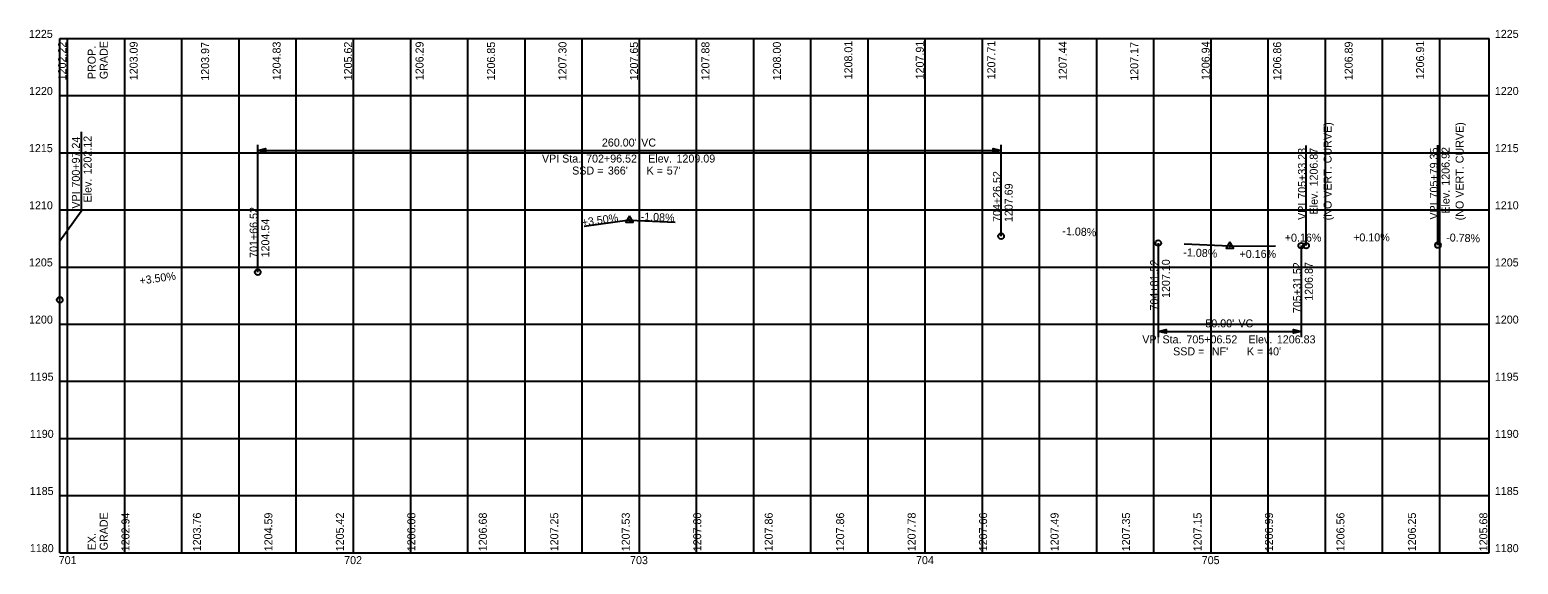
# Model space of a CAD drawing. Extents: x 65 to 585, y 1176 to 1363.
import ezdxf

# ---------------------------------------------------------------- set-up
doc = ezdxf.new("R2010")
doc.units = 0
for name, color, linetype in [('PF_P_Sta_Elev_Text', 7, 'Continuous'), ('PF_P_Text', 7, 'Continuous'), ('PF_P_Text_Strip_Grades_20', 7, 'Continuous'), ('PF_X_Text_Strip_Grade', 7, 'Continuous'), ('SH_Major_Grid_Line', 7, 'Continuous')]:
    doc.layers.add(name, color=color, linetype=linetype)

msp = doc.modelspace()

# ---------------------------------------------------------------- linework, layer by layer
at = {"layer": 'PF_P_Text'}
for p, q in [((144.39, 1278.18), (144.39, 1322.76)), ((404.39, 1290.76), (404.39, 1322.76)), ((557.22, 1287.66), (557.22, 1322.66)), ((144.39, 1320.86), (144.39, 1320.66)), ((144.39, 1320.76), (404.39, 1320.76)), ((404.39, 1320.66), (404.39, 1320.86)), ((511.1, 1287.48), (511.1, 1322.48)), ((75.11, 1268.48), (75.11, 1303.48)), ((274.39, 1296.38), (258.54, 1294.16)), ((274.39, 1296.38), (274.39, 1296.38)), ((274.39, 1296.38), (290.37, 1295.69)), ((459.39, 1288.39), (459.39, 1255.47)), ((484.39, 1287.31), (468.4, 1288)), ((484.39, 1287.31), (500.39, 1287.41)), ((484.39, 1287.31), (484.39, 1287.31)), ((509.39, 1287.47), (509.39, 1255.47)), ((459.39, 1257.57), (459.39, 1257.37)), ((459.39, 1257.47), (509.39, 1257.47)), ((509.39, 1257.37), (509.39, 1257.57))]:
    msp.add_line(p, q, dxfattribs=at)
msp.add_lwpolyline([(82.64, 1327.35), (82.64, 1299.4), (75.11, 1289.05)], dxfattribs=at)
for points in [[(144.39, 1320.76), (147.1, 1321.44), (147.1, 1320.08)], [(404.39, 1320.76), (401.67, 1320.08), (401.67, 1321.44)], [(274.39, 1297.82), (273.14, 1295.66), (275.64, 1295.66)], [(484.39, 1288.75), (483.14, 1286.58), (485.64, 1286.58)], [(459.39, 1257.47), (462.1, 1258.14), (462.1, 1256.79)], [(509.39, 1257.47), (506.67, 1256.79), (506.67, 1258.14)]]:
    msp.add_lwpolyline(points, close=True, dxfattribs=at)
for centre, radius in [((274.39, 1296.38), 0.1), ((274.39, 1296.38), 0.1), ((404.39, 1290.76), 1), ((459.39, 1288.39), 1), ((484.39, 1287.31), 0.1), ((484.39, 1287.31), 0.1), ((509.39, 1287.47), 1), ((511.1, 1287.48), 1), ((557.22, 1287.66), 1), ((144.39, 1278.18), 1), ((75.11, 1268.48), 1)]:
    msp.add_circle(centre, radius, dxfattribs=at)
at = {"layer": 'SH_Major_Grid_Line'}
for p, q in [((75.11, 1360), (575.11, 1360)), ((75.11, 1180), (75.11, 1360)), ((77.87, 1180), (77.87, 1360)), ((97.87, 1180), (97.87, 1360)), ((117.87, 1180), (117.87, 1360)), ((137.87, 1180), (137.87, 1360)), ((157.87, 1180), (157.87, 1360)), ((177.87, 1180), (177.87, 1360)), ((197.87, 1180), (197.87, 1360)), ((217.87, 1180), (217.87, 1360)), ((237.87, 1180), (237.87, 1360)), ((257.87, 1180), (257.87, 1360)), ((277.87, 1180), (277.87, 1360)), ((297.87, 1180), (297.87, 1360)), ((317.87, 1180), (317.87, 1360)), ((337.87, 1180), (337.87, 1360)), ((357.87, 1180), (357.87, 1360)), ((377.87, 1180), (377.87, 1360)), ((397.87, 1180), (397.87, 1360)), ((417.87, 1180), (417.87, 1360)), ((437.87, 1180), (437.87, 1360)), ((457.87, 1180), (457.87, 1360)), ((477.87, 1180), (477.87, 1360)), ((497.87, 1180), (497.87, 1360)), ((517.87, 1180), (517.87, 1360)), ((537.87, 1180), (537.87, 1360)), ((557.87, 1180), (557.87, 1360)), ((575.11, 1180), (575.11, 1360)), ((75.11, 1340), (575.11, 1340)), ((75.11, 1320), (575.11, 1320)), ((75.11, 1300), (575.11, 1300)), ((75.11, 1280), (575.11, 1280)), ((75.11, 1260), (575.11, 1260)), ((75.11, 1240), (575.11, 1240)), ((75.11, 1220), (575.11, 1220)), ((75.11, 1200), (575.11, 1200)), ((75.11, 1180), (575.11, 1180))]:
    msp.add_line(p, q, dxfattribs=at)

# ---------------------------------------------------------------- texts
at = {"layer": 'PF_P_Sta_Elev_Text'}
for s, p in [('1225', (64.34, 1360.2)), ('1225', (577.11, 1360.2)), ('1220', (64.37, 1340.2)), ('1220', (577.11, 1340.2)), ('1215', (64.34, 1320.2)), ('1215', (577.11, 1320.2)), ('1210', (64.37, 1300.2)), ('1210', (577.11, 1300.2)), ('1205', (64.34, 1280.2)), ('1205', (577.11, 1280.2)), ('1200', (64.37, 1260.2)), ('1200', (577.11, 1260.2)), ('1195', (64.63, 1240.2)), ('1195', (577.11, 1240.2)), ('1190', (64.66, 1220.2)), ('1190', (577.11, 1220.2)), ('1185', (64.63, 1200.2)), ('1185', (577.11, 1200.2)), ('1180', (64.66, 1180.2)), ('1180', (577.11, 1180.2)), ('701', (74.76, 1176)), ('702', (174.6, 1176)), ('703', (274.61, 1176)), ('704', (374.63, 1176)), ('705', (474.58, 1176))]:
    msp.add_text(s, height=2.8, dxfattribs=at).set_placement(p)
at = {"layer": 'PF_P_Text'}
for s, rotation, p in [('PROP.', 90, (87.7, 1345.76)), ('GRADE', 90, (91.9, 1345.76)), ('(NO VERT. CURVE)', 90, (520.01, 1296.34)), ('(NO VERT. CURVE)', 90, (566.19, 1296.34)), ('700+97.24', 90, (82.16, 1307.81)), ('1202.12', 90, (86.24, 1312.38)), ('705+33.23', 90, (511.05, 1303.88)), ('1206.87', 90, (515.15, 1308.19)), ('705+79.35', 90, (557.17, 1304)), ('1206.92', 90, (561.27, 1308.46)), ('704+26.52', 90, (404.34, 1295.76)), ('Elev. ', 90, (86.24, 1302.59)), ('1207.69', 90, (408.44, 1295.71)), ('VPI ', 90, (82.16, 1300.42)), ('VPI ', 90, (511.05, 1296.49)), ('Elev. ', 90, (515.15, 1298.41)), ('VPI ', 90, (557.17, 1296.61)), ('Elev. ', 90, (561.27, 1298.68)), ('701+66.52', 90, (144.34, 1283.18)), ('1204.54', 90, (148.42, 1283.35)), ('+3.50%', 7.9696, (257.92, 1294.18)), ('-1.08%', 357.5264, (278.26, 1296.31)), ('-1.08%', 357.5264, (425.77, 1291.24)), ('+0.16%', 0.3667, (503.63, 1288.83)), ('+0.10%', 0.2292, (527.54, 1288.94)), ('-0.78%', 358.213, (560.04, 1288.97)), ('-1.08%', 357.5264, (468.1, 1283.81)), ('704+81.52', 90, (459.34, 1264.77)), ('1207.10', 90, (463.44, 1269.16)), ('+0.16%', 0.3667, (487.8, 1283.13)), ('705+31.52', 90, (509.34, 1263.85)), ('1206.87', 90, (513.44, 1268.19)), ('+3.50%', 7.9696, (103.2, 1273.81)), ('GRADE', 90, (91.9, 1180.83)), ('EX. ', 90, (87.7, 1180.83))]:
    msp.add_text(s, height=2.8, rotation=rotation, dxfattribs=at).set_placement(p)
for s, p in [("260.00'", (264.76, 1322.16)), (' VC', (277.46, 1322.16)), ('VPI Sta. ', (243.79, 1316.56)), ('702+96.52', (259.23, 1316.56)), ('   Elev. ', (277.82, 1316.56)), ('1209.09', (290.86, 1316.56)), ('SSD = ', (254.35, 1312.36)), ("366'", (266.85, 1312.36)), ('K = ', (280.39, 1312.36)), ("57'", (287.45, 1312.36)), ("50.00'", (475.84, 1258.87)), (' VC', (486.37, 1258.87)), ('VPI Sta. ', (453.78, 1253.27)), ('705+06.52', (469.22, 1253.27)), ('   Elev. ', (487.81, 1253.27)), ('1206.83', (500.85, 1253.27)), ('SSD = ', (464.57, 1249.07)), ("INF'", (477.07, 1249.07)), ('K = ', (490.39, 1249.07)), ("40'", (497.45, 1249.07))]:
    msp.add_text(s, height=2.8, dxfattribs=at).set_placement(p)
at = {"layer": 'PF_P_Text_Strip_Grades_20'}
for s, p in [('1208.01', (352.37, 1345.67)), ('1208.01', (352.37, 1345.67)), ('1207.91', (377.37, 1345.67)), ('1207.91', (377.37, 1345.67)), ('1207.71', (402.37, 1345.67)), ('1207.71', (402.37, 1345.67)), ('1206.91', (552.37, 1345.67)), ('1206.91', (552.37, 1345.67)), ('1202.22', (77.37, 1345.34)), ('1202.22', (77.37, 1345.34)), ('1203.09', (102.37, 1345.38)), ('1203.09', (102.37, 1345.38)), ('1203.97', (127.37, 1345.21)), ('1203.97', (127.37, 1345.21)), ('1204.83', (152.37, 1345.36)), ('1204.83', (152.37, 1345.36)), ('1205.62', (177.37, 1345.34)), ('1205.62', (177.37, 1345.34)), ('1206.29', (202.37, 1345.38)), ('1206.29', (202.37, 1345.38)), ('1206.85', (227.37, 1345.3)), ('1206.85', (227.37, 1345.3)), ('1207.30', (252.37, 1345.33)), ('1207.30', (252.37, 1345.33)), ('1207.65', (277.37, 1345.3)), ('1207.65', (277.37, 1345.3)), ('1207.88', (302.37, 1345.33)), ('1207.88', (302.37, 1345.33)), ('1208.00', (327.37, 1345.33)), ('1208.00', (327.37, 1345.33)), ('1207.44', (427.37, 1345.41)), ('1207.44', (427.37, 1345.41)), ('1207.17', (452.37, 1345.21)), ('1207.17', (452.37, 1345.21)), ('1206.94', (477.37, 1345.41)), ('1206.94', (477.37, 1345.41)), ('1206.86', (502.37, 1345.32)), ('1206.86', (502.37, 1345.32)), ('1206.89', (527.37, 1345.38)), ('1206.89', (527.37, 1345.38))]:
    msp.add_text(s, height=2.8, rotation=90, dxfattribs=at).set_placement(p)
at = {"layer": 'PF_X_Text_Strip_Grade'}
for s, p in [('1202.94', (99.5, 1180.5)), ('1203.76', (124.5, 1180.5)), ('1204.59', (149.5, 1180.5)), ('1205.42', (174.5, 1180.5)), ('1206.08', (199.5, 1180.5)), ('1206.68', (224.5, 1180.5)), ('1207.25', (249.5, 1180.5)), ('1207.53', (274.5, 1180.5)), ('1207.80', (299.5, 1180.5)), ('1207.86', (324.5, 1180.5)), ('1207.86', (349.5, 1180.5)), ('1207.78', (374.5, 1180.5)), ('1207.66', (399.5, 1180.5)), ('1207.49', (424.5, 1180.5)), ('1207.35', (449.5, 1180.5)), ('1207.15', (474.5, 1180.5)), ('1206.99', (499.5, 1180.5)), ('1206.56', (524.5, 1180.5)), ('1206.25', (549.5, 1180.5)), ('1205.68', (574.5, 1180.5))]:
    msp.add_text(s, height=2.8, rotation=90, dxfattribs=at).set_placement(p)

doc.saveas('drawing.dxf')
